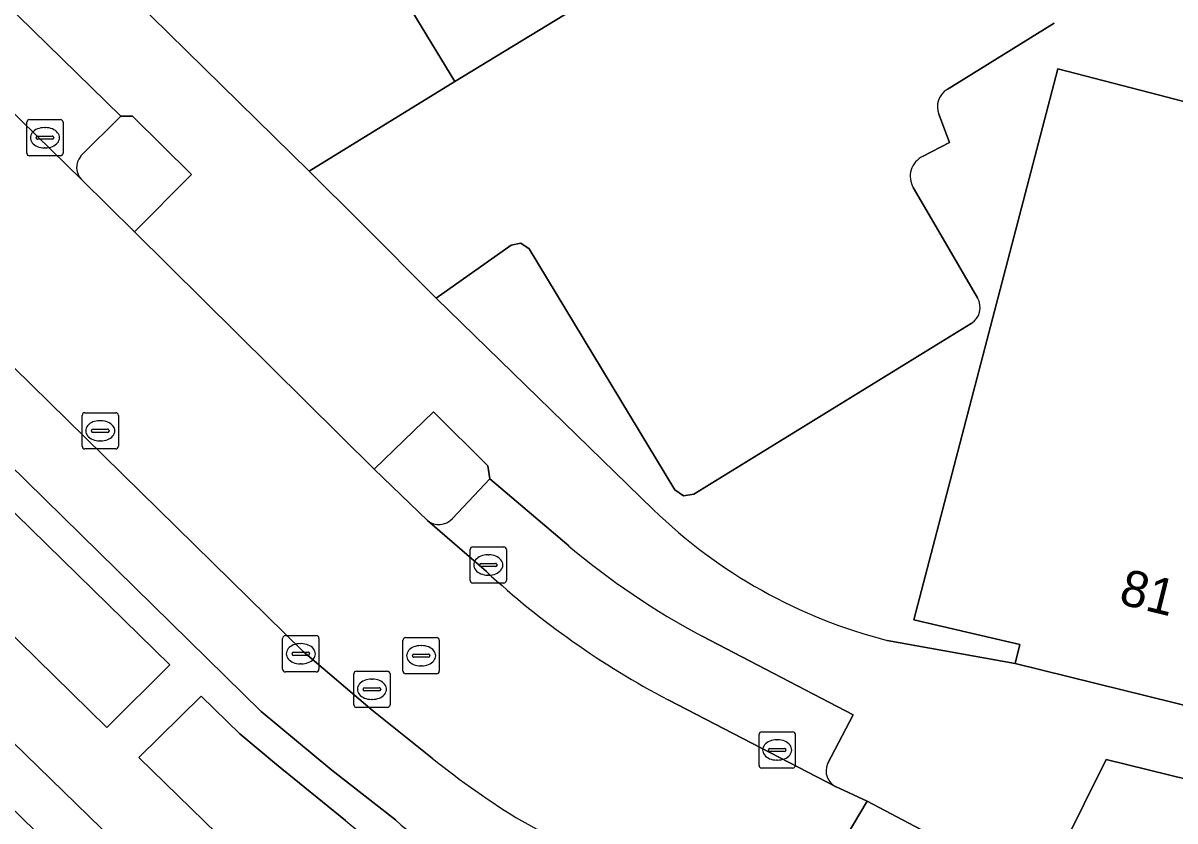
# Model space of a CAD drawing. Extents: x 159888 to 160761, y 384031 to 384750.
# Drawn here: x 160223.32 to 160255.09, y 384483.5 to 384505.51 of the extents above; entities that cross this region are included whole.
import ezdxf

# ---------------------------------------------------------------- set-up
doc = ezdxf.new("R2010")
doc.units = 0
for name, color, linetype in [('IMGEO_Erf', 7, 'Continuous'), ('IMGEO_Groenvoorziening', 7, 'Continuous'), ('IMGEO_Kolk', 7, 'Continuous'), ('IMGEO_Pand', 7, 'Continuous'), ('IMGEO_Pand_nummerreeks', 7, 'Continuous'), ('IMGEO_Parkeervlak_open', 7, 'Continuous'), ('IMGEO_Rijbaan_lokaal_open', 7, 'Continuous'), ('IMGEO_Rioolput', 7, 'Continuous'), ('IMGEO_Voetpad_open', 7, 'Continuous')]:
    doc.layers.add(name, color=color, linetype=linetype)

msp = doc.modelspace()

# ---------------------------------------------------------------- linework, layer by layer
at = {"layer": 'IMGEO_Erf'}
for points in [[(160209.436, 384522.798), (160231.216, 384501.429), (160235.233, 384503.903), (160233.656, 384506.495)], [(160251.757, 384505.512), (160248.804, 384503.682)], [(160247.154, 384488.478), (160250.68, 384487.841), (160250.81, 384488.365), (160247.887, 384489.05), (160251.86, 384504.251), (160254.627, 384503.529), (160260.827, 384501.91)], [(160248.575, 384502.993), (160248.872, 384502.218), (160248.127, 384501.832)], [(160247.87, 384500.974), (160248.438, 384500), (160249.644, 384497.93)], [(160249.464, 384497.221), (160241.821, 384492.51), (160241.53, 384492.463), (160241.292, 384492.636), (160237.275, 384499.28), (160237.052, 384499.438), (160236.785, 384499.383), (160234.712, 384497.923), (160240.701, 384492.09)]]:
    msp.add_lwpolyline(points, dxfattribs=at)
for centre, radius, start, end in [((160249.104, 384503.2), 0.568, 121.8653, 201.3646), ((160248.399, 384501.283), 0.612, 116.3246, 210.326), ((160249.193, 384497.667), 0.522, 301.2836, 30.2259), ((160250.679, 384502.346), 14.309, 225.7871, 255.7379)]:
    msp.add_arc(centre, radius, start, end, dxfattribs=at)
at = {"layer": 'IMGEO_Groenvoorziening'}
for points in [[(160226.022, 384502.938), (160224.91, 384501.836)], [(160224.94, 384501.185), (160226.392, 384499.753), (160227.966, 384501.332), (160226.336, 384502.94), (160226.022, 384502.938)], [(160235.16, 384491.842), (160236.194, 384492.935), (160236.135, 384493.293), (160234.638, 384494.783), (160233.004, 384493.205)], [(160233.004, 384493.205), (160234.472, 384491.786)], [(160228.232, 384486.943), (160226.515, 384485.249), (160234.069, 384477.876), (160236.663, 384480.473)], [(160232.209, 384483.512), (160230.311, 384485.052), (160229.301, 384485.902), (160228.232, 384486.943)], [(160253.804, 384480.534), (160260.823, 384478.737), (160261.82, 384483.067), (160253.188, 384485.188), (160251.37, 384481.523)]]:
    msp.add_lwpolyline(points, dxfattribs=at)
msp.add_lwpolyline([(160220.569, 384494.455), (160218.85, 384492.724), (160225.629, 384486.073), (160227.372, 384487.807)], close=True, dxfattribs=at)
for centre, radius, start, end in [((160225.284, 384501.527), 0.485, 140.4153, 224.8617), ((160234.787, 384492.173), 0.499, 230.8434, 318.4633), ((160249.569, 384504.171), 26.985, 229.96, 241.4279)]:
    msp.add_arc(centre, radius, start, end, dxfattribs=at)
at = {"layer": 'IMGEO_Kolk'}
for p, q in [((160223.424, 384501.921), (160223.424, 384502.773)), ((160223.499, 384502.847), (160224.351, 384502.847)), ((160224.425, 384502.773), (160224.425, 384501.921)), ((160223.683, 384502.341), (160223.683, 384502.353)), ((160223.726, 384502.39), (160224.124, 384502.39)), ((160223.912, 384502.627), (160223.937, 384502.627)), ((160224.167, 384502.353), (160224.167, 384502.341)), ((160224.121, 384502.304), (160223.723, 384502.304)), ((160223.935, 384502.067), (160223.91, 384502.067)), ((160224.351, 384501.847), (160223.499, 384501.847)), ((160235.65, 384490.133), (160235.65, 384490.985)), ((160235.725, 384491.059), (160236.577, 384491.059)), ((160236.651, 384490.985), (160236.651, 384490.133)), ((160235.909, 384490.553), (160235.909, 384490.565)), ((160235.952, 384490.602), (160236.35, 384490.602)), ((160236.138, 384490.839), (160236.163, 384490.839)), ((160236.393, 384490.565), (160236.393, 384490.553)), ((160236.347, 384490.516), (160235.949, 384490.516)), ((160236.161, 384490.279), (160236.136, 384490.279)), ((160236.577, 384490.059), (160235.725, 384490.059)), ((160230.48, 384487.683), (160230.48, 384488.535)), ((160230.555, 384488.609), (160231.407, 384488.609)), ((160230.968, 384488.389), (160230.993, 384488.389)), ((160231.481, 384488.535), (160231.481, 384487.683)), ((160230.739, 384488.103), (160230.739, 384488.115)), ((160231.177, 384488.066), (160230.779, 384488.066)), ((160230.782, 384488.152), (160231.18, 384488.152)), ((160231.223, 384488.115), (160231.223, 384488.103)), ((160230.991, 384487.829), (160230.966, 384487.829)), ((160231.407, 384487.609), (160230.555, 384487.609)), ((160243.617, 384485.03), (160243.617, 384485.882)), ((160243.692, 384485.956), (160244.544, 384485.956)), ((160244.618, 384485.882), (160244.618, 384485.03)), ((160243.919, 384485.499), (160244.317, 384485.499)), ((160244.105, 384485.736), (160244.13, 384485.736)), ((160243.876, 384485.45), (160243.876, 384485.462)), ((160244.314, 384485.413), (160243.916, 384485.413)), ((160244.128, 384485.176), (160244.103, 384485.176)), ((160244.36, 384485.462), (160244.36, 384485.45)), ((160244.544, 384484.956), (160243.692, 384484.956))]:
    msp.add_line(p, q, dxfattribs=at)
for points in [[(160223.424, 384501.921), (160223.424, 384502.773)], [(160223.499, 384502.847), (160224.351, 384502.847)], [(160224.425, 384502.773), (160224.425, 384501.921)], [(160224.351, 384501.847), (160223.499, 384501.847)], [(160235.65, 384490.133), (160235.65, 384490.985)], [(160235.725, 384491.059), (160236.577, 384491.059)], [(160236.651, 384490.985), (160236.651, 384490.133)], [(160236.577, 384490.059), (160235.725, 384490.059)], [(160230.48, 384487.683), (160230.48, 384488.535)], [(160230.555, 384488.609), (160231.407, 384488.609)], [(160231.481, 384488.535), (160231.481, 384487.683)], [(160231.407, 384487.609), (160230.555, 384487.609)], [(160243.617, 384485.03), (160243.617, 384485.882)], [(160243.692, 384485.956), (160244.544, 384485.956)], [(160244.618, 384485.882), (160244.618, 384485.03)], [(160244.544, 384484.956), (160243.692, 384484.956)]]:
    msp.add_lwpolyline(points, dxfattribs=at)
for centre, radius, start, end in [((160223.501, 384502.771), 0.0765, 91.552, 178.448), ((160223.501, 384502.771), 0.0765, 91.552, 178.448), ((160224.349, 384502.771), 0.0765, 1.552, 88.448), ((160224.349, 384502.771), 0.0765, 1.552, 88.448), ((160223.723, 384502.35), 0.0403, 85.8775, 175.7526), ((160223.72, 384502.34), 0.0366, 178.938, 274.7102), ((160224.124, 384502.347), 0.043, 264.8664, 352.4533), ((160224.128, 384502.352), 0.0386, 1.7309, 96.639), ((160223.501, 384501.923), 0.0765, 181.552, 268.448), ((160223.501, 384501.923), 0.0765, 181.552, 268.448), ((160224.349, 384501.923), 0.0765, 271.552, 358.448), ((160224.349, 384501.923), 0.0765, 271.552, 358.448), ((160235.727, 384490.983), 0.0765, 91.552, 178.448), ((160235.727, 384490.983), 0.0765, 91.552, 178.448), ((160236.575, 384490.983), 0.0765, 1.552, 88.448), ((160236.575, 384490.983), 0.0765, 1.552, 88.448), ((160235.949, 384490.562), 0.0403, 85.8775, 175.7526), ((160236.354, 384490.564), 0.0386, 1.7309, 96.639), ((160235.946, 384490.552), 0.0366, 178.938, 274.7102), ((160236.35, 384490.559), 0.043, 264.8664, 352.4533), ((160235.727, 384490.135), 0.0765, 181.552, 268.448), ((160235.727, 384490.135), 0.0765, 181.552, 268.448), ((160236.575, 384490.135), 0.0765, 271.552, 358.448), ((160236.575, 384490.135), 0.0765, 271.552, 358.448), ((160230.557, 384488.533), 0.0765, 91.552, 178.448), ((160230.557, 384488.533), 0.0765, 91.552, 178.448), ((160231.405, 384488.533), 0.0765, 1.552, 88.448), ((160231.405, 384488.533), 0.0765, 1.552, 88.448), ((160230.779, 384488.112), 0.0403, 85.8775, 175.7526), ((160230.776, 384488.102), 0.0366, 178.938, 274.7102), ((160231.18, 384488.109), 0.043, 264.8664, 352.4533), ((160231.184, 384488.114), 0.0386, 1.7309, 96.639), ((160230.557, 384487.685), 0.0765, 181.552, 268.448), ((160230.557, 384487.685), 0.0765, 181.552, 268.448), ((160231.405, 384487.685), 0.0765, 271.552, 358.448), ((160231.405, 384487.685), 0.0765, 271.552, 358.448), ((160243.694, 384485.88), 0.0765, 91.552, 178.448), ((160243.694, 384485.88), 0.0765, 91.552, 178.448), ((160244.542, 384485.88), 0.0765, 1.552, 88.448), ((160244.542, 384485.88), 0.0765, 1.552, 88.448), ((160243.916, 384485.459), 0.0403, 85.8775, 175.7526), ((160244.321, 384485.461), 0.0386, 1.7309, 96.639), ((160243.913, 384485.449), 0.0366, 178.938, 274.7102), ((160244.317, 384485.456), 0.043, 264.8664, 352.4533), ((160243.694, 384485.032), 0.0765, 181.552, 268.448), ((160243.694, 384485.032), 0.0765, 181.552, 268.448), ((160244.542, 384485.032), 0.0765, 271.552, 358.448), ((160244.542, 384485.032), 0.0765, 271.552, 358.448)]:
    msp.add_arc(centre, radius, start, end, dxfattribs=at)
for centre, major_axis, ratio, start_param, end_param in [((160223.911, 384502.347), (-0.387, 0.002), 0.722429, 4.712389, 7.853982), ((160223.936, 384502.347), (-0.39, 0.002), 0.717154, 1.570796, 4.712389), ((160236.137, 384490.559), (-0.387, 0.002), 0.722429, 4.712389, 7.853982), ((160236.162, 384490.559), (-0.39, 0.002), 0.717154, 1.570796, 4.712389), ((160230.967, 384488.109), (-0.387, 0.002), 0.722429, 4.712389, 7.853982), ((160230.992, 384488.109), (-0.39, 0.002), 0.717154, 1.570796, 4.712389), ((160244.104, 384485.456), (-0.387, 0.002), 0.722429, 4.712389, 7.853982), ((160244.129, 384485.456), (-0.39, 0.002), 0.717154, 1.570796, 4.712389)]:
    msp.add_ellipse(centre, major_axis=major_axis, ratio=ratio, start_param=start_param, end_param=end_param, dxfattribs=at)
at = {"layer": 'IMGEO_Pand'}
for points in [[(160235.233, 384503.903), (160238.466, 384505.869), (160238.269, 384506.193), (160248.414, 384512.365), (160240.21, 384525.85), (160237.931, 384524.463), (160235.324, 384528.748), (160238.073, 384530.42), (160236.574, 384532.884), (160233.385, 384530.944), (160233.612, 384530.57), (160223.372, 384524.341), (160231.527, 384510.936), (160233.87, 384512.362), (160236.417, 384508.175), (160233.656, 384506.495)], [(160260.181, 384499.308), (160260.353, 384500), (160260.7, 384501.399), (160260.827, 384501.91), (160254.627, 384503.529), (160251.86, 384504.251), (160247.887, 384489.05), (160250.81, 384488.365), (160250.68, 384487.841), (160256.565, 384486.387), (160258.573, 384494.483), (160258.961, 384494.387)], [(160218.725, 384488.027), (160212.699, 384481.844), (160220.289, 384474.445), (160226.316, 384480.627)]]:
    msp.add_lwpolyline(points, close=True, dxfattribs=at)
at = {"layer": 'IMGEO_Parkeervlak_open'}
for points in [[(160224.91, 384501.836), (160226.022, 384502.938), (160209.434, 384519.16)], [(160207.717, 384518.046), (160224.94, 384501.185)], [(160234.606, 384485.229), (160232.947, 384486.549), (160231.049, 384488.176), (160203.557, 384515.169)], [(160203.589, 384514.481), (160202.511, 384513.401), (160229.885, 384486.517), (160231.834, 384484.894), (160233.589, 384483.523)], [(160251.931, 384506.246), (160248.414, 384512.365), (160238.269, 384506.193), (160238.466, 384505.869), (160235.233, 384503.903), (160231.216, 384501.429), (160232.647, 384500), (160234.712, 384497.923), (160236.785, 384499.383), (160237.052, 384499.438), (160237.275, 384499.28), (160241.292, 384492.636), (160241.53, 384492.463), (160241.821, 384492.51), (160249.464, 384497.221)], [(160248.804, 384503.682), (160251.757, 384505.512)], [(160248.127, 384501.832), (160248.872, 384502.218), (160248.575, 384502.993)], [(160249.644, 384497.93), (160248.438, 384500), (160247.87, 384500.974)], [(160236.194, 384492.935), (160235.16, 384491.842)], [(160238.371, 384491.083), (160236.194, 384492.935)], [(160234.472, 384491.786), (160236.102, 384490.375)], [(160245.502, 384485.069), (160246.211, 384486.424), (160242.052, 384488.591)], [(160241.108, 384486.842), (160245.725, 384484.446)]]:
    msp.add_lwpolyline(points, dxfattribs=at)
for centre, radius, start, end in [((160249.104, 384503.2), 0.568, 121.8653, 201.3646), ((160225.284, 384501.527), 0.485, 140.4153, 224.8617), ((160248.399, 384501.283), 0.612, 116.3246, 210.326), ((160249.193, 384497.667), 0.522, 301.2836, 30.2259), ((160234.787, 384492.173), 0.499, 230.8434, 318.4633), ((160252.112, 384507.415), 21.344, 229.9252, 241.8796), ((160251.906, 384507.455), 23.27, 227.2222, 242.3525), ((160249.235, 384503.425), 23.347, 231.2012, 238.603), ((160245.965, 384484.883), 0.499, 158.1488, 241.2403), ((160243.239, 384494.56), 14.66, 228.835, 242.1271)]:
    msp.add_arc(centre, radius, start, end, dxfattribs=at)
at = {"layer": 'IMGEO_Rijbaan_lokaal_open'}
for points in [[(160236.102, 384490.375), (160234.472, 384491.786), (160233.004, 384493.205), (160226.392, 384499.753), (160224.94, 384501.185), (160207.717, 384518.046)], [(160202.743, 384515.892), (160203.557, 384515.169), (160231.049, 384488.176), (160232.947, 384486.549), (160234.606, 384485.229)], [(160237.072, 384483.496), (160243.137, 384480.12), (160243.99, 384479.65), (160246.602, 384484.042), (160245.725, 384484.446), (160241.108, 384486.842)], [(160251.709, 384481.364), (160251.37, 384481.523), (160246.602, 384484.042), (160243.99, 384479.65), (160244.847, 384479.061), (160248.032, 384476.537)]]:
    msp.add_lwpolyline(points, dxfattribs=at)
for centre, radius, start, end in [((160251.906, 384507.455), 23.27, 227.2222, 242.3525), ((160249.235, 384503.425), 23.347, 231.2012, 238.603)]:
    msp.add_arc(centre, radius, start, end, dxfattribs=at)
at = {"layer": 'IMGEO_Rioolput'}
for p, q in [((160225.025, 384494.761), (160225.877, 384494.761)), ((160224.95, 384493.835), (160224.95, 384494.687)), ((160225.438, 384494.541), (160225.463, 384494.541)), ((160225.951, 384494.687), (160225.951, 384493.835)), ((160225.209, 384494.255), (160225.209, 384494.267)), ((160225.647, 384494.218), (160225.249, 384494.218)), ((160225.252, 384494.304), (160225.65, 384494.304)), ((160225.693, 384494.267), (160225.693, 384494.255)), ((160225.877, 384493.761), (160225.025, 384493.761)), ((160225.461, 384493.981), (160225.436, 384493.981)), ((160233.799, 384487.629), (160233.799, 384488.481)), ((160233.874, 384488.555), (160234.726, 384488.555)), ((160234.8, 384488.481), (160234.8, 384487.629)), ((160234.058, 384488.049), (160234.058, 384488.061)), ((160234.101, 384488.098), (160234.499, 384488.098)), ((160234.287, 384488.335), (160234.312, 384488.335)), ((160234.542, 384488.061), (160234.542, 384488.049)), ((160234.496, 384488.012), (160234.098, 384488.012)), ((160234.31, 384487.775), (160234.285, 384487.775)), ((160232.441, 384486.704), (160232.441, 384487.556)), ((160232.516, 384487.63), (160233.368, 384487.63)), ((160232.929, 384487.41), (160232.954, 384487.41)), ((160233.442, 384487.556), (160233.442, 384486.704)), ((160234.726, 384487.555), (160233.874, 384487.555)), ((160232.7, 384487.124), (160232.7, 384487.136)), ((160233.138, 384487.087), (160232.74, 384487.087)), ((160232.743, 384487.173), (160233.141, 384487.173)), ((160233.184, 384487.136), (160233.184, 384487.124)), ((160232.952, 384486.85), (160232.927, 384486.85)), ((160233.368, 384486.63), (160232.516, 384486.63))]:
    msp.add_line(p, q, dxfattribs=at)
for points in [[(160225.025, 384494.761), (160225.877, 384494.761)], [(160224.95, 384493.835), (160224.95, 384494.687)], [(160225.951, 384494.687), (160225.951, 384493.835)], [(160225.877, 384493.761), (160225.025, 384493.761)], [(160233.799, 384487.629), (160233.799, 384488.481)], [(160233.874, 384488.555), (160234.726, 384488.555)], [(160234.8, 384488.481), (160234.8, 384487.629)], [(160232.441, 384486.704), (160232.441, 384487.556)], [(160232.516, 384487.63), (160233.368, 384487.63)], [(160233.442, 384487.556), (160233.442, 384486.704)], [(160234.726, 384487.555), (160233.874, 384487.555)], [(160233.368, 384486.63), (160232.516, 384486.63)]]:
    msp.add_lwpolyline(points, dxfattribs=at)
for centre, radius, start, end in [((160225.027, 384494.685), 0.0765, 91.552, 178.448), ((160225.027, 384494.685), 0.0765, 91.552, 178.448), ((160225.875, 384494.685), 0.0765, 1.552, 88.448), ((160225.875, 384494.685), 0.0765, 1.552, 88.448), ((160225.249, 384494.264), 0.0403, 85.8775, 175.7526), ((160225.246, 384494.254), 0.0366, 178.938, 274.7102), ((160225.65, 384494.261), 0.043, 264.8664, 352.4533), ((160225.654, 384494.266), 0.0386, 1.7309, 96.639), ((160225.027, 384493.837), 0.0765, 181.552, 268.448), ((160225.027, 384493.837), 0.0765, 181.552, 268.448), ((160225.875, 384493.837), 0.0765, 271.552, 358.448), ((160225.875, 384493.837), 0.0765, 271.552, 358.448), ((160233.876, 384488.479), 0.0765, 91.552, 178.448), ((160233.876, 384488.479), 0.0765, 91.552, 178.448), ((160234.724, 384488.479), 0.0765, 1.552, 88.448), ((160234.724, 384488.479), 0.0765, 1.552, 88.448), ((160234.098, 384488.058), 0.0403, 85.8775, 175.7526), ((160234.095, 384488.048), 0.0366, 178.938, 274.7102), ((160234.499, 384488.055), 0.043, 264.8664, 352.4533), ((160234.503, 384488.06), 0.0386, 1.7309, 96.639), ((160232.518, 384487.554), 0.0765, 91.552, 178.448), ((160232.518, 384487.554), 0.0765, 91.552, 178.448), ((160233.366, 384487.554), 0.0765, 1.552, 88.448), ((160233.366, 384487.554), 0.0765, 1.552, 88.448), ((160233.876, 384487.631), 0.0765, 181.552, 268.448), ((160233.876, 384487.631), 0.0765, 181.552, 268.448), ((160234.724, 384487.631), 0.0765, 271.552, 358.448), ((160234.724, 384487.631), 0.0765, 271.552, 358.448), ((160232.74, 384487.133), 0.0403, 85.8775, 175.7526), ((160232.737, 384487.123), 0.0366, 178.938, 274.7102), ((160233.141, 384487.13), 0.043, 264.8664, 352.4533), ((160233.145, 384487.135), 0.0386, 1.7309, 96.639), ((160232.518, 384486.706), 0.0765, 181.552, 268.448), ((160232.518, 384486.706), 0.0765, 181.552, 268.448), ((160233.366, 384486.706), 0.0765, 271.552, 358.448), ((160233.366, 384486.706), 0.0765, 271.552, 358.448)]:
    msp.add_arc(centre, radius, start, end, dxfattribs=at)
for centre, major_axis, ratio, start_param, end_param in [((160225.437, 384494.261), (-0.387, 0.002), 0.722429, 4.712389, 7.853982), ((160225.462, 384494.261), (-0.39, 0.002), 0.717154, 1.570796, 4.712389), ((160234.286, 384488.055), (-0.387, 0.002), 0.722429, 4.712389, 7.853982), ((160234.311, 384488.055), (-0.39, 0.002), 0.717154, 1.570796, 4.712389), ((160232.928, 384487.13), (-0.387, 0.002), 0.722429, 4.712389, 7.853982), ((160232.953, 384487.13), (-0.39, 0.002), 0.717154, 1.570796, 4.712389)]:
    msp.add_ellipse(centre, major_axis=major_axis, ratio=ratio, start_param=start_param, end_param=end_param, dxfattribs=at)
at = {"layer": 'IMGEO_Voetpad_open'}
for points in [[(160240.701, 384492.09), (160234.712, 384497.923), (160232.647, 384500), (160231.216, 384501.429), (160209.436, 384522.798), (160209.415, 384522.819), (160209.351, 384522.892), (160209.293, 384522.971), (160209.242, 384523.054), (160209.199, 384523.142), (160209.165, 384523.233), (160209.138, 384523.327), (160209.12, 384523.423), (160209.111, 384523.52), (160209.11, 384523.617), (160209.114, 384523.662), (160205.077, 384522.566)], [(160206.42, 384519.384), (160207.949, 384520.971), (160209.478, 384519.428), (160209.434, 384519.16), (160226.022, 384502.938), (160226.336, 384502.94), (160227.966, 384501.332), (160226.392, 384499.753), (160233.004, 384493.205), (160234.638, 384494.783), (160236.135, 384493.293), (160236.194, 384492.935), (160238.371, 384491.083)], [(160195.384, 384516.714), (160196.41, 384511.643), (160196.722, 384511.338), (160208.326, 384500), (160242.988, 384466.237), (160244.045, 384468.12), (160234.942, 384477.032), (160237.752, 384479.861), (160242.643, 384477.209), (160243.35, 384478.526), (160246.899, 384475.68)], [(160233.589, 384483.523), (160231.834, 384484.894), (160229.885, 384486.517), (160202.511, 384513.401), (160203.589, 384514.481)], [(160196.415, 384509.815), (160203.556, 384502.837), (160211.139, 384495.429), (160214.063, 384492.572), (160218.725, 384488.027), (160226.316, 384480.627), (160229.825, 384477.206), (160233.908, 384473.231), (160241.079, 384466.248), (160241.5, 384465.937), (160236.032, 384456.726), (160234.136, 384453.532), (160230.493, 384447.455), (160224.977, 384438.17), (160219.443, 384428.854), (160218.975, 384429.14), (160217.802, 384427.216), (160218.9, 384425.95), (160242.463, 384465.36), (160242.988, 384466.237), (160208.326, 384500), (160196.722, 384511.338)], [(160242.052, 384488.591), (160246.211, 384486.424), (160245.502, 384485.069)], [(160329.273, 384468.85), (160328.957, 384468.924), (160324.589, 384469.942), (160323.615, 384470.169), (160320.202, 384470.965), (160318.799, 384471.294), (160317.826, 384471.523), (160312.033, 384472.883), (160300.376, 384475.627), (160294.547, 384477.036), (160293.586, 384477.267), (160288.393, 384478.525), (160283.54, 384479.7), (160283.188, 384479.786), (160282.145, 384480.041), (160276.201, 384481.496), (160274.889, 384481.817), (160269.153, 384483.256), (160263.339, 384484.714), (160262.354, 384484.957), (160256.565, 384486.387), (160250.68, 384487.841), (160247.154, 384488.478)], [(160236.663, 384480.473), (160234.069, 384477.876), (160226.515, 384485.249), (160228.232, 384486.943)], [(160228.232, 384486.943), (160229.301, 384485.902), (160230.311, 384485.052), (160232.209, 384483.512)], [(160245.725, 384484.446), (160246.602, 384484.042), (160251.37, 384481.523), (160253.188, 384485.188), (160261.82, 384483.067), (160260.823, 384478.737), (160261.719, 384478.514), (160262.62, 384478.305)]]:
    msp.add_lwpolyline(points, dxfattribs=at)
msp.add_lwpolyline([(160220.569, 384494.455), (160227.372, 384487.807), (160225.629, 384486.073), (160218.85, 384492.724)], close=True, dxfattribs=at)
for centre, radius, start, end in [((160250.679, 384502.346), 14.309, 225.7871, 255.7379), ((160252.112, 384507.415), 21.344, 229.9252, 241.8796), ((160245.965, 384484.883), 0.499, 158.1488, 241.2403), ((160249.569, 384504.171), 26.985, 229.96, 241.4279), ((160243.239, 384494.56), 14.66, 228.835, 242.1271)]:
    msp.add_arc(centre, radius, start, end, dxfattribs=at)

# ---------------------------------------------------------------- texts
at = {"layer": 'IMGEO_Pand_nummerreeks'}
msp.add_text('81', height=1, rotation=346.0771, dxfattribs=at).set_placement((160253.508, 384489.497))

doc.saveas('drawing.dxf')
